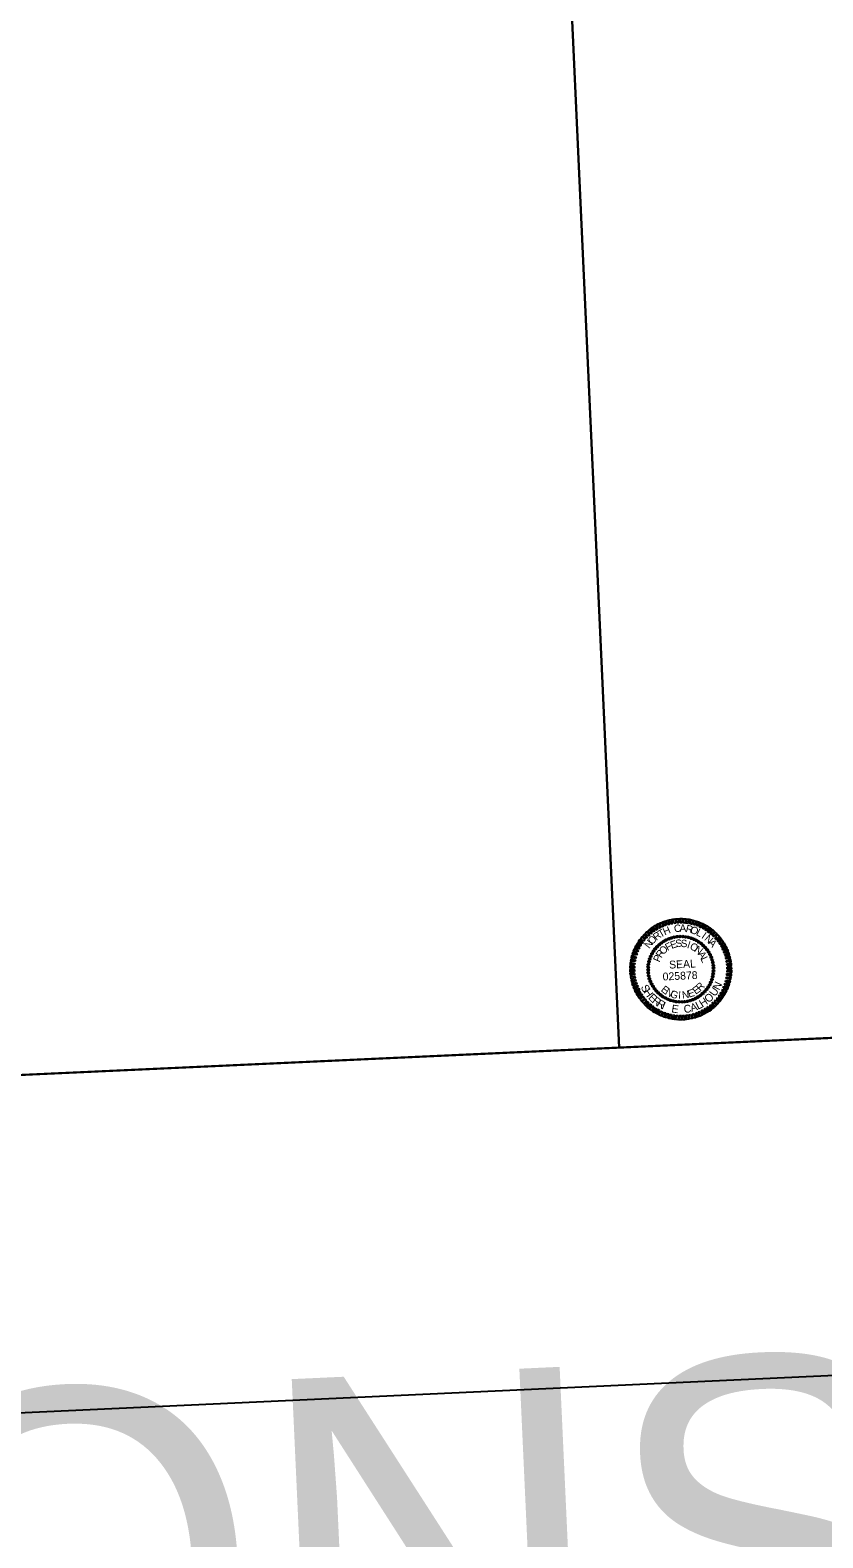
# Model space of a CAD drawing. Extents: x 1191067 to 1191874, y 892813 to 893283.
# Drawn here: x 1191742.66 to 1191747.52, y 893208.38 to 893217.62 of the extents above; entities that cross this region are included whole.
import ezdxf

# ---------------------------------------------------------------- set-up
doc = ezdxf.new("R2010")
doc.units = 0
for name, color, linetype in [('Sheet Border Standard 30in CELL', 7, 'Continuous'), ('Sheet Clip Boundary CELL', 7, 'Continuous'), ('Sheet PE Seal Cell', 7, 'Continuous'), ('Sheet Sticker Exception Certification CELL', 7, 'Continuous')]:
    doc.layers.add(name, color=color, linetype=linetype)

# ---------------------------------------------------------------- blocks, each defined once
blk = doc.blocks.new('STICKER EXCEPTION CERTIFICATION')
at = {"layer": 'Sheet Sticker Exception Certification CELL'}
blk.add_line((0, 0), (4.00075, 0), dxfattribs=at)
blk.add_text('DOCUMENT NOT CONSIDERED FINAL', height=0.11, dxfattribs=at).set_placement((0.42142, -0.20691))

msp = doc.modelspace()

# ---------------------------------------------------------------- linework, layer by layer
at = {"layer": 'Sheet Border Standard 30in CELL'}
msp.add_line((1191744.2132, 893256.3356), (1191746.2689, 893211.4026), dxfattribs=at)
for points in [[(1191744.2132, 893256.3356), (1191784.1714, 893258.1637), (1191786.2281, 893213.2107), (1191746.2699, 893211.3826)], [(1191704.2351, 893254.5066), (1191744.2132, 893256.3356), (1191746.2699, 893211.3826), (1191706.2917, 893209.5536)]]:
    msp.add_lwpolyline(points, close=True, dxfattribs=at)
at = {"layer": 'Sheet Clip Boundary CELL'}
msp.add_lwpolyline([(1191202.887, 892905.773), (1191187.2617, 893244.0767), (1191701.2697, 893267.8174), (1191704.0618, 893207.3645), (1191782.8613, 893211.0041), (1191795.7055, 892932.9156), (1191477.6168, 892917.9494)], close=True, dxfattribs=at)
at = {"layer": 'Sheet PE Seal Cell'}
for p, q in [((1191746.5585, 893212.0426), (1191746.5585, 893212.0426)), ((1191746.5742, 893212.0497), (1191746.5742, 893212.0497)), ((1191746.5908, 893212.0553), (1191746.5908, 893212.0553)), ((1191746.6082, 893212.0593), (1191746.6082, 893212.0593)), ((1191746.6253, 893212.0624), (1191746.6253, 893212.0624)), ((1191746.6428, 893212.0636), (1191746.6428, 893212.0636)), ((1191746.6605, 893212.0632), (1191746.6605, 893212.0632)), ((1191746.6778, 893212.0612), (1191746.6778, 893212.0612)), ((1191746.6947, 893212.0584), (1191746.6947, 893212.0584)), ((1191746.7118, 893212.0536), (1191746.7118, 893212.0536)), ((1191746.7281, 893212.0471), (1191746.7281, 893212.0471)), ((1191746.744, 893212.0398), (1191746.744, 893212.0398)), ((1191746.4715, 893211.9585), (1191746.4715, 893211.9585)), ((1191746.4808, 893211.9733), (1191746.4808, 893211.9733)), ((1191746.491, 893211.9878), (1191746.491, 893211.9878)), ((1191746.5024, 893212.0008), (1191746.5024, 893212.0008)), ((1191746.515, 893212.0133), (1191746.515, 893212.0133)), ((1191746.5285, 893212.024), (1191746.5285, 893212.024)), ((1191746.5433, 893212.0339), (1191746.5433, 893212.0339)), ((1191746.7589, 893212.0305), (1191746.7589, 893212.0305)), ((1191746.7734, 893212.0204), (1191746.7734, 893212.0204)), ((1191746.7863, 893212.0089), (1191746.7863, 893212.0089)), ((1191746.7989, 893211.9963), (1191746.7989, 893211.9963)), ((1191746.8095, 893211.9828), (1191746.8095, 893211.9828)), ((1191746.8194, 893211.968), (1191746.8194, 893211.968)), ((1191746.8281, 893211.9528), (1191746.8281, 893211.9528)), ((1191746.4477, 893211.8573), (1191746.4477, 893211.8573)), ((1191746.4481, 893211.8749), (1191746.4481, 893211.8749)), ((1191746.4501, 893211.8923), (1191746.4501, 893211.8923)), ((1191746.4529, 893211.9092), (1191746.4529, 893211.9092)), ((1191746.4577, 893211.9262), (1191746.4577, 893211.9262)), ((1191746.4642, 893211.9426), (1191746.4642, 893211.9426)), ((1191746.6484, 893211.8629), (1191746.6484, 893211.8629)), ((1191746.8352, 893211.9371), (1191746.8352, 893211.9371)), ((1191746.8408, 893211.9205), (1191746.8408, 893211.9205)), ((1191746.8448, 893211.9031), (1191746.8448, 893211.9031)), ((1191746.848, 893211.886), (1191746.848, 893211.886)), ((1191746.8492, 893211.8685), (1191746.8492, 893211.8685)), ((1191746.4489, 893211.8397), (1191746.4489, 893211.8397)), ((1191746.4521, 893211.8227), (1191746.4521, 893211.8227)), ((1191746.4561, 893211.8052), (1191746.4561, 893211.8052)), ((1191746.4616, 893211.7887), (1191746.4616, 893211.7887)), ((1191746.4688, 893211.773), (1191746.4688, 893211.773)), ((1191746.8254, 893211.7673), (1191746.8254, 893211.7673)), ((1191746.8327, 893211.7832), (1191746.8327, 893211.7832)), ((1191746.8391, 893211.7995), (1191746.8391, 893211.7995)), ((1191746.8439, 893211.8166), (1191746.8439, 893211.8166)), ((1191746.8468, 893211.8335), (1191746.8468, 893211.8335)), ((1191746.8488, 893211.8508), (1191746.8488, 893211.8508)), ((1191746.4775, 893211.7578), (1191746.4775, 893211.7578)), ((1191746.4873, 893211.743), (1191746.4873, 893211.743)), ((1191746.498, 893211.7295), (1191746.498, 893211.7295)), ((1191746.5106, 893211.7168), (1191746.5106, 893211.7168)), ((1191746.5235, 893211.7054), (1191746.5235, 893211.7054)), ((1191746.538, 893211.6953), (1191746.538, 893211.6953)), ((1191746.5528, 893211.6859), (1191746.5528, 893211.6859)), ((1191746.5688, 893211.6787), (1191746.5688, 893211.6787)), ((1191746.5851, 893211.6722), (1191746.5851, 893211.6722)), ((1191746.7061, 893211.6705), (1191746.7061, 893211.6705)), ((1191746.7226, 893211.6761), (1191746.7226, 893211.6761)), ((1191746.7383, 893211.6832), (1191746.7383, 893211.6832)), ((1191746.7536, 893211.6919), (1191746.7536, 893211.6919)), ((1191746.7683, 893211.7018), (1191746.7683, 893211.7018)), ((1191746.7818, 893211.7124), (1191746.7818, 893211.7124)), ((1191746.7945, 893211.725), (1191746.7945, 893211.725)), ((1191746.8059, 893211.738), (1191746.8059, 893211.738)), ((1191746.8161, 893211.7524), (1191746.8161, 893211.7524)), ((1191746.6021, 893211.6674), (1191746.6021, 893211.6674)), ((1191746.6191, 893211.6645), (1191746.6191, 893211.6645)), ((1191746.6364, 893211.6625), (1191746.6364, 893211.6625)), ((1191746.654, 893211.6621), (1191746.654, 893211.6621)), ((1191746.6716, 893211.6633), (1191746.6716, 893211.6633)), ((1191746.6886, 893211.6665), (1191746.6886, 893211.6665))]:
    msp.add_line(p, q, dxfattribs=at)
for points in [[(1191746.5125, 893212.1125), (1191746.4987, 893212.1343), (1191746.5108, 893212.1405), (1191746.5211, 893212.1165)], [(1191746.5297, 893212.1217), (1191746.5182, 893212.1444), (1191746.53, 893212.1498), (1191746.5396, 893212.1246)], [(1191746.549, 893212.129), (1191746.5387, 893212.1526), (1191746.5509, 893212.1567), (1191746.5572, 893212.1322)], [(1191746.5679, 893212.1351), (1191746.5584, 893212.1599), (1191746.5718, 893212.1633), (1191746.5762, 893212.1375)], [(1191746.5869, 893212.1404), (1191746.5793, 893212.1656), (1191746.5925, 893212.1674), (1191746.5964, 893212.142)], [(1191746.606, 893212.1436), (1191746.6004, 893212.169), (1191746.6139, 893212.1712), (1191746.6155, 893212.1453)], [(1191746.6258, 893212.1466), (1191746.6227, 893212.1724), (1191746.6359, 893212.1726), (1191746.6354, 893212.1466)], [(1191746.645, 893212.147), (1191746.6439, 893212.173), (1191746.6571, 893212.1732), (1191746.6546, 893212.1471)], [(1191746.6651, 893212.1467), (1191746.6655, 893212.1728), (1191746.6788, 893212.171), (1191746.6747, 893212.1456)], [(1191746.6844, 893212.1444), (1191746.6868, 893212.1702), (1191746.7001, 893212.1688), (1191746.694, 893212.1437)], [(1191746.705, 893212.141), (1191746.7078, 893212.1671), (1191746.7215, 893212.1645), (1191746.7135, 893212.1393)], [(1191746.7244, 893212.1366), (1191746.7293, 893212.1617), (1191746.7418, 893212.1583), (1191746.7329, 893212.1342)], [(1191746.7427, 893212.1303), (1191746.7507, 893212.1559), (1191746.7622, 893212.1516), (1191746.752, 893212.1279)], [(1191746.761, 893212.1235), (1191746.7699, 893212.1475), (1191746.7826, 893212.1425), (1191746.77, 893212.1195)], [(1191746.7798, 893212.1152), (1191746.7896, 893212.1384), (1191746.8019, 893212.1322), (1191746.7876, 893212.1107)], [(1191746.4114, 893212.0194), (1191746.3892, 893212.032), (1191746.3963, 893212.044), (1191746.4163, 893212.0272)], [(1191746.4227, 893212.0352), (1191746.4012, 893212.0498), (1191746.4095, 893212.0606), (1191746.428, 893212.0426)], [(1191746.436, 893212.051), (1191746.4149, 893212.0664), (1191746.4245, 893212.0761), (1191746.4421, 893212.0577)], [(1191746.4486, 893212.0656), (1191746.4302, 893212.0823), (1191746.4393, 893212.0924), (1191746.4559, 893212.0715)], [(1191746.464, 893212.0787), (1191746.4459, 893212.0971), (1191746.4563, 893212.106), (1191746.4713, 893212.0842)], [(1191746.4786, 893212.0914), (1191746.4629, 893212.1111), (1191746.4729, 893212.1191), (1191746.4872, 893212.0966)], [(1191746.4957, 893212.1022), (1191746.48, 893212.1231), (1191746.4921, 893212.13), (1191746.5031, 893212.1073)], [(1191746.7959, 893212.1051), (1191746.8088, 893212.1289), (1191746.8196, 893212.121), (1191746.8049, 893212.1007)], [(1191746.8128, 893212.0938), (1191746.8266, 893212.1165), (1191746.8374, 893212.1082), (1191746.8207, 893212.0886)], [(1191746.8286, 893212.0822), (1191746.844, 893212.1037), (1191746.8541, 893212.0945), (1191746.8365, 893212.0765)], [(1191746.8436, 893212.0688), (1191746.8599, 893212.0884), (1191746.87, 893212.0792), (1191746.8499, 893212.0627)], [(1191746.8583, 893212.0551), (1191746.8758, 893212.0739), (1191746.8847, 893212.0635), (1191746.8642, 893212.0473)], [(1191746.871, 893212.04), (1191746.8898, 893212.0577), (1191746.8979, 893212.0465), (1191746.8761, 893212.0327)], [(1191746.8821, 893212.0241), (1191746.9026, 893212.0403), (1191746.9107, 893212.0286), (1191746.8881, 893212.0164)], [(1191746.3719, 893211.9291), (1191746.3469, 893211.9332), (1191746.3491, 893211.9465), (1191746.3747, 893211.9377)], [(1191746.377, 893211.9486), (1191746.3519, 893211.9546), (1191746.3566, 893211.9673), (1191746.381, 893211.9572)], [(1191746.3842, 893211.9665), (1191746.359, 893211.9746), (1191746.3644, 893211.9872), (1191746.3878, 893211.9755)], [(1191746.3914, 893211.9853), (1191746.3681, 893211.9942), (1191746.3736, 893212.0069), (1191746.3958, 893211.9931)], [(1191746.4002, 893212.0029), (1191746.3772, 893212.0139), (1191746.3847, 893212.0254), (1191746.4062, 893212.0104)], [(1191746.8933, 893212.007), (1191746.915, 893212.022), (1191746.9208, 893212.0099), (1191746.8984, 893211.9997)], [(1191746.9021, 893211.9902), (1191746.9251, 893212.0033), (1191746.9309, 893211.9907), (1191746.9065, 893211.9816)], [(1191746.9101, 893211.9718), (1191746.934, 893211.9833), (1191746.939, 893211.9711), (1191746.9145, 893211.9636)], [(1191746.9174, 893211.9529), (1191746.9426, 893211.9632), (1191746.9456, 893211.9502), (1191746.9206, 893211.9446)], [(1191746.3642, 893211.8699), (1191746.3382, 893211.8695), (1191746.3384, 893211.8827), (1191746.3646, 893211.8795)], [(1191746.3647, 893211.8499), (1191746.3388, 893211.8475), (1191746.3382, 893211.8611), (1191746.3643, 893211.8595)], [(1191746.3653, 893211.8892), (1191746.3396, 893211.8904), (1191746.3406, 893211.9041), (1191746.3669, 893211.8989)], [(1191746.3676, 893211.9097), (1191746.3427, 893211.9118), (1191746.3449, 893211.9255), (1191746.3704, 893211.9182)], [(1191746.9231, 893211.9339), (1191746.9479, 893211.9427), (1191746.9509, 893211.9292), (1191746.9259, 893211.9256)], [(1191746.9275, 893211.9149), (1191746.9533, 893211.9217), (1191746.9551, 893211.9081), (1191746.9296, 893211.9054)], [(1191746.9308, 893211.8958), (1191746.9566, 893211.9002), (1191746.9581, 893211.8867), (1191746.9321, 893211.8863)], [(1191746.9321, 893211.8759), (1191746.9581, 893211.8783), (1191746.9587, 893211.8647), (1191746.9326, 893211.8663)], [(1191746.9326, 893211.8559), (1191746.9587, 893211.8563), (1191746.9585, 893211.843), (1191746.9323, 893211.8462)], [(1191746.366, 893211.8299), (1191746.3402, 893211.8256), (1191746.3388, 893211.8391), (1191746.3648, 893211.8395)], [(1191746.3693, 893211.8109), (1191746.3436, 893211.8041), (1191746.3418, 893211.8176), (1191746.3673, 893211.8204)], [(1191746.3738, 893211.7919), (1191746.349, 893211.7831), (1191746.3459, 893211.7966), (1191746.371, 893211.8001)], [(1191746.3795, 893211.7729), (1191746.3543, 893211.7625), (1191746.3513, 893211.7756), (1191746.3763, 893211.7812)], [(1191746.3867, 893211.754), (1191746.3628, 893211.7425), (1191746.3579, 893211.7547), (1191746.3824, 893211.7622)], [(1191746.9198, 893211.7772), (1191746.9449, 893211.7711), (1191746.9403, 893211.7585), (1191746.9158, 893211.7686)], [(1191746.9249, 893211.7967), (1191746.95, 893211.7926), (1191746.9478, 893211.7793), (1191746.9221, 893211.7881)], [(1191746.9293, 893211.8161), (1191746.9542, 893211.814), (1191746.952, 893211.8003), (1191746.9264, 893211.8075)], [(1191746.9315, 893211.8366), (1191746.9572, 893211.8354), (1191746.9562, 893211.8217), (1191746.93, 893211.8269)], [(1191746.3948, 893211.7356), (1191746.3718, 893211.7225), (1191746.366, 893211.735), (1191746.3904, 893211.7442)], [(1191746.4036, 893211.7187), (1191746.3818, 893211.7037), (1191746.3761, 893211.7159), (1191746.3984, 893211.7261)], [(1191746.4148, 893211.7016), (1191746.3943, 893211.6855), (1191746.3861, 893211.6971), (1191746.4088, 893211.7094)], [(1191746.4259, 893211.6857), (1191746.4071, 893211.6681), (1191746.399, 893211.6793), (1191746.4208, 893211.6931)], [(1191746.4386, 893211.6707), (1191746.421, 893211.6519), (1191746.4122, 893211.6623), (1191746.4326, 893211.6784)], [(1191746.8608, 893211.6748), (1191746.882, 893211.6593), (1191746.8724, 893211.6497), (1191746.8547, 893211.6681)], [(1191746.8741, 893211.6906), (1191746.8956, 893211.676), (1191746.8873, 893211.6652), (1191746.8689, 893211.6832)], [(1191746.8854, 893211.7064), (1191746.9076, 893211.6938), (1191746.9006, 893211.6818), (1191746.8806, 893211.6985)], [(1191746.8967, 893211.7229), (1191746.9196, 893211.7119), (1191746.9121, 893211.7004), (1191746.8906, 893211.7154)], [(1191746.9055, 893211.7405), (1191746.9287, 893211.7316), (1191746.9233, 893211.7189), (1191746.901, 893211.7327)], [(1191746.9126, 893211.7593), (1191746.9378, 893211.7512), (1191746.9324, 893211.7385), (1191746.909, 893211.7503)], [(1191746.4532, 893211.657), (1191746.4369, 893211.6374), (1191746.4269, 893211.6465), (1191746.447, 893211.6631)], [(1191746.4683, 893211.6436), (1191746.4528, 893211.6221), (1191746.4428, 893211.6312), (1191746.4604, 893211.6493)], [(1191746.484, 893211.6319), (1191746.4702, 893211.6093), (1191746.4594, 893211.6176), (1191746.4762, 893211.6372)], [(1191746.5009, 893211.6207), (1191746.488, 893211.5969), (1191746.4772, 893211.6048), (1191746.4919, 893211.6251)], [(1191746.517, 893211.6106), (1191746.5073, 893211.5873), (1191746.495, 893211.5936), (1191746.5092, 893211.6151)], [(1191746.5358, 893211.6023), (1191746.5269, 893211.5782), (1191746.5143, 893211.5833), (1191746.5268, 893211.6063)], [(1191746.5542, 893211.5955), (1191746.5461, 893211.5699), (1191746.5347, 893211.5742), (1191746.5448, 893211.5979)], [(1191746.5725, 893211.5891), (1191746.5676, 893211.5641), (1191746.555, 893211.5675), (1191746.5639, 893211.5915)], [(1191746.5919, 893211.5848), (1191746.5891, 893211.5587), (1191746.5753, 893211.5612), (1191746.5834, 893211.5864)], [(1191746.6125, 893211.5813), (1191746.61, 893211.5556), (1191746.5968, 893211.557), (1191746.6028, 893211.5821)], [(1191746.6318, 893211.579), (1191746.6314, 893211.553), (1191746.6181, 893211.5548), (1191746.6221, 893211.5802)], [(1191746.6518, 893211.5787), (1191746.653, 893211.5528), (1191746.6398, 893211.5526), (1191746.6422, 893211.5787)], [(1191746.671, 893211.5792), (1191746.6742, 893211.5533), (1191746.661, 893211.5531), (1191746.6614, 893211.5792)], [(1191746.6909, 893211.5821), (1191746.6965, 893211.5568), (1191746.683, 893211.5545), (1191746.6814, 893211.5805)], [(1191746.71, 893211.5854), (1191746.7175, 893211.5601), (1191746.7044, 893211.5583), (1191746.7004, 893211.5838)], [(1191746.729, 893211.5907), (1191746.7385, 893211.5659), (1191746.725, 893211.5625), (1191746.7207, 893211.5883)], [(1191746.7479, 893211.5968), (1191746.7582, 893211.5732), (1191746.746, 893211.569), (1191746.7396, 893211.5936)], [(1191746.7672, 893211.604), (1191746.7786, 893211.5813), (1191746.7669, 893211.576), (1191746.7573, 893211.6012)], [(1191746.7844, 893211.6132), (1191746.7982, 893211.5914), (1191746.7861, 893211.5853), (1191746.7758, 893211.6092)], [(1191746.8011, 893211.6236), (1191746.8169, 893211.6027), (1191746.8048, 893211.5958), (1191746.7938, 893211.6185)], [(1191746.8182, 893211.6344), (1191746.834, 893211.6147), (1191746.8239, 893211.6066), (1191746.8097, 893211.6292)], [(1191746.8329, 893211.6471), (1191746.8509, 893211.6287), (1191746.8405, 893211.6198), (1191746.8255, 893211.6415)], [(1191746.8483, 893211.6602), (1191746.8667, 893211.6434), (1191746.8575, 893211.6334), (1191746.841, 893211.6543)]]:
    msp.add_lwpolyline(points, close=True, dxfattribs=at)
for centre, major_axis in [((1191746.5432, 893212.0337), (-0.00302, 0.0049)), ((1191746.5585, 893212.0423), (-0.00258, 0.00515)), ((1191746.5745, 893212.0494), (-0.00212, 0.00535)), ((1191746.591, 893212.0551), (-0.00165, 0.00552)), ((1191746.608, 893212.0594), (-0.00116, 0.00564)), ((1191746.6253, 893212.0622), (-0.00066, 0.00572)), ((1191746.6428, 893212.0634), (-0.00016, 0.00576)), ((1191746.6603, 893212.0632), (0.00034, 0.00575)), ((1191746.6777, 893212.0614), (0.00084, 0.0057)), ((1191746.6949, 893212.0581), (0.00133, 0.0056)), ((1191746.7117, 893212.0533), (0.00182, 0.00547)), ((1191746.7281, 893212.0471), (0.00229, 0.00529)), ((1191746.7438, 893212.0394), (0.00274, 0.00507)), ((1191746.4643, 893211.9425), (-0.00529, 0.00229)), ((1191746.4719, 893211.9583), (-0.00507, 0.00274)), ((1191746.4809, 893211.9733), (-0.00481, 0.00317)), ((1191746.4911, 893211.9875), (-0.00452, 0.00358)), ((1191746.5026, 893212.0007), (-0.00419, 0.00396)), ((1191746.5152, 893212.0129), (-0.00383, 0.00431)), ((1191746.5287, 893212.0239), (-0.00344, 0.00462)), ((1191746.7588, 893212.0304), (0.00317, 0.00481)), ((1191746.773, 893212.0202), (0.00358, 0.00452)), ((1191746.7862, 893212.0087), (0.00396, 0.00419)), ((1191746.7984, 893211.9961), (0.00431, 0.00383)), ((1191746.8095, 893211.9826), (0.00462, 0.00344)), ((1191746.8193, 893211.9681), (0.0049, 0.00302)), ((1191746.8278, 893211.9528), (0.00515, 0.00258)), ((1191746.4479, 893211.8572), (-0.00576, -0.00016)), ((1191746.4481, 893211.8747), (-0.00575, 0.00034)), ((1191746.4499, 893211.8921), (-0.0057, 0.00084)), ((1191746.4532, 893211.9093), (-0.0056, 0.00133)), ((1191746.458, 893211.9262), (-0.00547, 0.00182)), ((1191746.835, 893211.9368), (0.00535, 0.00212)), ((1191746.8407, 893211.9203), (0.00552, 0.00165)), ((1191746.845, 893211.9033), (0.00564, 0.00116)), ((1191746.8477, 893211.886), (0.00572, 0.00066)), ((1191746.8487, 893211.8511), (0.00575, -0.00034)), ((1191746.849, 893211.8686), (0.00576, 0.00016)), ((1191746.4491, 893211.8398), (-0.00572, -0.00066)), ((1191746.4519, 893211.8225), (-0.00564, -0.00116)), ((1191746.4562, 893211.8055), (-0.00552, -0.00165)), ((1191746.4619, 893211.789), (-0.00535, -0.00212)), ((1191746.4691, 893211.773), (-0.00515, -0.00258)), ((1191746.4776, 893211.7577), (-0.0049, -0.00302)), ((1191746.825, 893211.7675), (0.00507, -0.00274)), ((1191746.8326, 893211.7833), (0.00529, -0.00229)), ((1191746.8388, 893211.7996), (0.00547, -0.00182)), ((1191746.8436, 893211.8165), (0.0056, -0.00133)), ((1191746.8469, 893211.8336), (0.0057, -0.00084)), ((1191746.4874, 893211.7432), (-0.00462, -0.00344)), ((1191746.4984, 893211.7296), (-0.00431, -0.00383)), ((1191746.5106, 893211.7171), (-0.00396, -0.00419)), ((1191746.5239, 893211.7056), (-0.00358, -0.00452)), ((1191746.538, 893211.6953), (-0.00317, -0.00481)), ((1191746.5531, 893211.6864), (-0.00274, -0.00507)), ((1191746.5688, 893211.6787), (-0.00229, -0.00529)), ((1191746.5852, 893211.6725), (-0.00182, -0.00547)), ((1191746.602, 893211.6677), (-0.00133, -0.0056)), ((1191746.6192, 893211.6644), (-0.00084, -0.0057)), ((1191746.6716, 893211.6636), (0.00066, -0.00572)), ((1191746.6888, 893211.6664), (0.00116, -0.00564)), ((1191746.7058, 893211.6706), (0.00165, -0.00552)), ((1191746.7224, 893211.6764), (0.00212, -0.00535)), ((1191746.7383, 893211.6835), (0.00258, -0.00515)), ((1191746.7536, 893211.692), (0.00302, -0.0049)), ((1191746.7681, 893211.7019), (0.00344, -0.00462)), ((1191746.7817, 893211.7129), (0.00383, -0.00431)), ((1191746.7943, 893211.7251), (0.00419, -0.00396)), ((1191746.8057, 893211.7383), (0.00452, -0.00358)), ((1191746.816, 893211.7525), (0.00481, -0.00317)), ((1191746.6366, 893211.6626), (-0.00034, -0.00575)), ((1191746.6541, 893211.6623), (0.00016, -0.00576))]:
    msp.add_ellipse(centre, major_axis=major_axis, ratio=0.999708, dxfattribs=at)

# ---------------------------------------------------------------- block references
at = {"layer": 'Sheet Sticker Exception Certification CELL', "xscale": 20, "yscale": 19.999999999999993, "rotation": 2.619466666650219}
msp.add_blockref('STICKER EXCEPTION CERTIFICATION', (1191706.2917, 893209.5536), dxfattribs=at)

# ---------------------------------------------------------------- texts
at = {"layer": 'Sheet PE Seal Cell'}
for s, height, rotation, p in [('C', 0.0451, 8.83934, (1191746.6105, 893212.0882)), ('A', 0.0451, 1.63979, (1191746.6419, 893212.092)), ('R', 0.0451, 347.24056, (1191746.6756, 893212.092)), ('N', 0.0451, 52.04297, (1191746.455, 893211.9862)), ('O', 0.0451, 44.84121, (1191746.4723, 893212.0102)), ('R', 0.0451, 37.63997, (1191746.4988, 893212.0362)), ('T', 0.0451, 30.43924, (1191746.5251, 893212.0551)), ('H', 0.0451, 23.23894, (1191746.5505, 893212.0694)), ('E', 0.0451, 19.23053, (1191746.5927, 893211.9869)), ('S', 0.0451, 9.87507, (1191746.6199, 893211.9965)), ('S', 0.0451, 0.51987, (1191746.6486, 893211.9982)), ('O', 0.0451, 340.04063, (1191746.7026, 893212.0872)), ('L', 0.0451, 332.84034, (1191746.7385, 893212.074)), ('I', 0.0451, 325.63961, (1191746.7717, 893212.0563)), ('N', 0.0451, 318.43837, (1191746.7895, 893212.0447)), ('A', 0.0451, 311.23662, (1191746.8141, 893212.0222)), ('P', 0.0451, 66.01836, (1191746.5177, 893211.9026)), ('R', 0.0451, 56.65912, (1191746.5293, 893211.9287)), ('O', 0.0451, 47.30071, (1191746.5424, 893211.9489)), ('F', 0.0451, 28.5865, (1191746.5677, 893211.9737)), ('I', 0.0451, 341.80907, (1191746.6833, 893211.9942)), ('O', 0.0451, 332.45295, (1191746.6995, 893211.9894)), ('N', 0.0451, 323.09608, (1191746.727, 893211.9746)), ('A', 0.0451, 304.37973, (1191746.7507, 893211.9549)), ('SEAL', 0.04799, 2.61947, (1191746.5778, 893211.8665)), ('L', 0.0451, 295.02032, (1191746.7676, 893211.928)), ('S', 0.048, 297.48401, (1191746.4013, 893211.7538)), ('E', 0.0451, 320.89636, (1191746.5231, 893211.7318)), ('025878', 0.04799, 2.61947, (1191746.5383, 893211.7937)), ('E', 0.0451, 35.74356, (1191746.7401, 893211.7061)), ('R', 0.0451, 45.10087, (1191746.7676, 893211.7262)), ('N', 0.048, 64.3548, (1191746.884, 893211.7307)), ('H', 0.048, 304.80972, (1191746.4172, 893211.7231)), ('E', 0.048, 314.79371, (1191746.445, 893211.6852)), ('R', 0.048, 321.90305, (1191746.4685, 893211.6614)), ('R', 0.048, 329.38331, (1191746.4963, 893211.6396)), ('N', 0.0451, 330.25342, (1191746.5481, 893211.7113)), ('G', 0.0451, 339.60971, (1191746.5792, 893211.6947)), ('I', 0.0451, 358.32067, (1191746.6323, 893211.682)), ('N', 0.0451, 7.67586, (1191746.6591, 893211.682)), ('E', 0.0451, 17.03123, (1191746.6984, 893211.6886)), ('H', 0.048, 32.87279, (1191746.7803, 893211.6271)), ('O', 0.048, 42.85678, (1191746.8192, 893211.6535)), ('U', 0.048, 54.41718, (1191746.8577, 893211.692)), ('I', 0.048, 336.86357, (1191746.5266, 893211.6217)), ('E', 0.048, 350.86588, (1191746.5886, 893211.5994)), ('C', 0.048, 8.17557, (1191746.6697, 893211.5936)), ('A', 0.048, 17.75772, (1191746.7142, 893211.6009)), ('L', 0.048, 26.59803, (1191746.7537, 893211.6141))]:
    msp.add_text(s, height=height, rotation=rotation, dxfattribs=at).set_placement(p)

doc.saveas('drawing.dxf')
